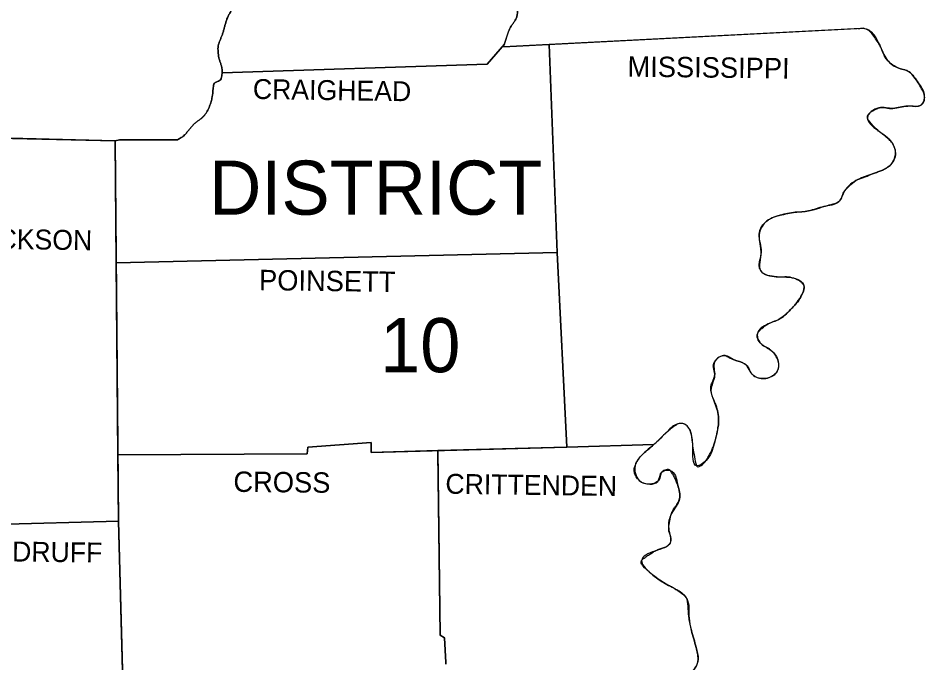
# Model space of a CAD drawing. Extents: x -28335 to 1228743, y -22428 to 152440.
# Drawn here: x 33833 to 38164, y 12816 to 15894 of the extents above; entities that cross this region are included whole.
import ezdxf

# ---------------------------------------------------------------- set-up
doc = ezdxf.new("R2010")
doc.units = 0
doc.layers.add('R_Draft', color=7, linetype='Continuous')
doc.layers.add('R_No Plot', color=7, linetype='Continuous')

msp = doc.modelspace()

# ---------------------------------------------------------------- linework, layer by layer
at = {"layer": 'R_Draft'}
msp.add_line((36152.1, 15757.7), (36176.5, 15832.9), dxfattribs=at)
for points in [[(33229.3, 17459.6), (33220.8, 17391), (33266.1, 17384.2), (33263.8, 17357), (33315.9, 17345.7), (33320.4, 17309.4), (33345.4, 17293.6), (33352.2, 17184.8), (33481.3, 17171.2), (33481.3, 17073.8), (33528.9, 17067), (33528.9, 17028.5), (33569.6, 17017.2), (33567.4, 16885.8), (33603.6, 16879), (33612.7, 16582.3), (33420.1, 16564.2), (33422.4, 16500.7), (33363.5, 16498.5), (33383.9, 15329.6), (34296.8, 15309.2), (34312.6, 13492.5), (33716.9, 13476.6), (33705, 13796)], [(36152.1, 15757.7), (37871.4, 15846.1)], [(34807.8, 15632.9), (36072.8, 15673.9), (36155.9, 15769.7)], [(36369, 15768.9), (36408.1, 14774.6), (36454.1, 13846.6)], [(34593.5, 15313.7), (34317.2, 15313.7), (34296.8, 15309.2)], [(36408.1, 14774.6), (34301.9, 14726.6)], [(34309.9, 13809.5), (35214.2, 13814.2), (35216.5, 13845.9), (35520.1, 13868.5), (35520.1, 13820.9), (36869.5, 13858)], [(35837.1, 13829.7), (35848.5, 12948.8), (35868.9, 12935.2), (35876.1, 12809.9)], [(35837.2, 13820.9), (35848.5, 12948.8), (35868.9, 12935.2), (35875.7, 12817.4)], [(35837.2, 13820.9), (35848.5, 12948.8), (35868.9, 12935.2), (35875.7, 12817.4)], [(35837.2, 13820.9), (35848.5, 12948.8), (35868.9, 12935.2), (35875.7, 12817.4)], [(35837.2, 13820.9), (35848.5, 12948.8), (35868.9, 12935.2), (35875.7, 12817.4)], [(34312.6, 13492.5), (34346.6, 12251.1), (33807.5, 12248.9), (33805.2, 12199), (33648.9, 12190), (33635.3, 11931.7), (33420.5, 11931.7)]]:
    msp.add_lwpolyline(points, dxfattribs=at)
for points in [[(36695.7, 17526.9), (36697.7, 17501.9), (36700.3, 17476.9), (36703.5, 17452.1), (36707.1, 17427.2), (36712.4, 17413.2), (36721.5, 17400.5), (36731.4, 17388.2), (36738.8, 17375.1), (36741.7, 17352.1), (36738.8, 17327.3), (36737.1, 17302.7), (36738.8, 17291), (36743.3, 17280), (36760.5, 17257.7), (36781.8, 17239.2), (36798, 17228.4), (36814.8, 17218.9), (36831.5, 17209.4), (36847.5, 17198.4), (36880.2, 17169.4), (36894.2, 17152.5), (36900.5, 17143), (36906.4, 17132.7), (36914.6, 17113.6), (36919.4, 17094.2), (36921.1, 17074.9), (36920, 17055.7), (36916.1, 17035.9), (36910.5, 17016.2), (36905.1, 16996.4), (36901.9, 16976.4), (36900.6, 16954.4), (36899.9, 16932.3), (36899, 16910.2), (36897.4, 16888.1), (36888.3, 16811.1), (36884, 16775.6), (36880.5, 16758.1), (36878, 16749.4), (36874.7, 16740.8), (36851.1, 16709.5), (36820.3, 16684.2), (36807.3, 16673.9), (36794.1, 16664), (36781, 16653.9), (36768.2, 16643.4), (36720.7, 16595.9), (36711.8, 16583.7), (36704.1, 16570.5), (36696.2, 16557.6), (36686.7, 16546), (36627.8, 16491.7), (36568.9, 16435), (36521.3, 16385.2), (36508.3, 16370.2), (36496.2, 16354.5), (36484.8, 16338.3), (36473.7, 16321.8), (36466.8, 16304.8), (36463.4, 16286), (36459.6, 16267.5), (36456.2, 16259.1), (36451.1, 16251.6), (36438.5, 16238.6), (36425.1, 16226.5), (36411.7, 16214.5), (36399, 16201.7), (36358.2, 16156.4), (36303.8, 16095.3), (36294.9, 16081.3), (36288.7, 16065.6), (36283.3, 16049.4), (36276.7, 16034.1), (36264.5, 16016.2), (36250.3, 15999.2), (36236.3, 15982.2), (36224.6, 15963.9), (36219.7, 15947.6), (36218.3, 15930.1), (36217.3, 15912.4), (36213.2, 15895.9), (36205.9, 15881.9), (36196.9, 15868.4), (36187.6, 15855.1), (36179.3, 15841.5), (36176.5, 15832.9)], [(35025.5, 16260.4), (35006.3, 16232.9), (34990, 16204), (34982.9, 16188.2), (34976.8, 16172), (34970.6, 16155.9), (34962.8, 16140.6), (34950.1, 16121.9), (34936.1, 16104.1), (34921.9, 16086.4), (34908.4, 16068.1), (34886.5, 16033.8), (34876.6, 16016.1), (34867.6, 15997.8), (34864.6, 15986.3), (34863.9, 15974.1), (34863.3, 15961.9), (34860.9, 15950.3), (34853.5, 15934.3), (34844.6, 15918.7), (34836, 15903.1), (34829.1, 15886.9), (34824.4, 15871.1), (34820, 15855.1), (34815.7, 15839.2), (34811, 15823.4), (34806.1, 15809.8), (34800.6, 15796.3), (34795.2, 15782.8), (34790.6, 15769.1), (34788.1, 15755.1), (34787.7, 15740.8), (34788.8, 15726.5), (34790.6, 15712.4), (34793.7, 15698.2), (34798.3, 15684), (34802.9, 15669.9), (34806.5, 15655.8), (34807.9, 15642.9), (34807.5, 15629.7), (34805.6, 15616.6), (34804, 15610.1), (34802, 15603.7), (34795.1, 15596), (34784.5, 15591.2), (34774.1, 15586.5), (34768, 15578.8), (34766.2, 15570.7), (34765, 15562.6), (34763.4, 15546), (34761.8, 15529.4), (34758.9, 15513.1), (34753, 15490.3), (34745.3, 15467.8), (34732.7, 15443.7), (34724.9, 15432.8), (34715.9, 15422.5), (34705.5, 15413.3), (34694.4, 15405.2), (34683.2, 15397.2), (34672.8, 15388.5), (34661.2, 15375.9), (34650.4, 15362.5), (34639.5, 15349.1), (34627.5, 15336.4), (34611.6, 15323.8), (34602.9, 15318.6), (34593.5, 15313.7)], [(37846.5, 15843.8), (37871.4, 15846.1), (37948.5, 15764.5), (37982.4, 15696.6), (38032.3, 15658.1), (38088.9, 15637.7), (38131.9, 15585.6), (38161.4, 15528.9), (38145.5, 15479.1), (38082.1, 15474.6), (38011.9, 15463.3), (37943.9, 15465.5), (37889.6, 15420.2), (37939.4, 15359), (38005.1, 15302.4), (38023.2, 15241.3), (37987, 15182.4), (37914.5, 15150.6), (37844.3, 15123.5), (37780.8, 15069.1), (37751.4, 15017), (37681.2, 14994.3), (37608.7, 14974), (37545.2, 14967.2), (37472.7, 14953.6), (37402.5, 14919.6), (37373.1, 14860.7), (37382.1, 14776.9), (37379.9, 14688.5), (37454.6, 14659.1), (37520.3, 14656.8), (37583.7, 14622.8), (37576.9, 14573), (37529.4, 14509.6), (37472.7, 14459.7), (37416.1, 14434.8), (37364, 14387.3), (37382.1, 14339.7), (37429.7, 14308), (37463.7, 14255.9), (37459.2, 14208.3), (37404.8, 14174.3), (37345.9, 14187.9), (37302.8, 14244.5), (37253, 14262.7), (37210, 14283.1), (37160.1, 14253.6), (37160.1, 14187.9), (37142, 14117.7), (37157.9, 14065.6), (37178.3, 13993.1), (37176, 13938.7), (37157.9, 13861.7), (37119.4, 13782.4), (37074.1, 13757.5), (37055.9, 13843.6), (37046.9, 13913.8), (37019.7, 13954.6), (36983.4, 13956.9), (36935.9, 13922.9), (36883.8, 13870.8), (36818.1, 13814.2), (36779.6, 13757.5), (36799.9, 13687.3), (36849.8, 13669.2), (36888.3, 13682.8), (36908.7, 13728.1), (36947.2, 13734.9), (36983.4, 13664.6)], [(36983.4, 13664.6), (36992.5, 13599), (36954, 13528.7), (36940.4, 13458.5), (36947.2, 13388.3), (36874.7, 13349.8), (36811.3, 13304.5), (36847.5, 13250.1), (36915.5, 13200.3), (36983.4, 13161.8), (37026.5, 13123.3), (37037.8, 13030.4), (37049.1, 12971.5), (37071.8, 12889.9), (37080.8, 12833.3), (37040.1, 12765.3), (36992.5, 12751.8), (36942.7, 12767.6), (36883.8, 12772.1), (36836.2, 12726.8), (36802.2, 12663.4), (36768.2, 12600), (36743.3, 12545.6), (36718.4, 12486.7), (36668.6, 12418.8), (36607.4, 12407.4), (36534.9, 12389.3), (36491.9, 12339.5), (36498.7, 12255.7), (36539.4, 12199), (36571.2, 12128.8), (36593.8, 12067.6), (36582.5, 11990.6), (36550.8, 11934), (36510, 11900), (36491.9, 11827.5), (36462.4, 11773.2), (36435.2, 11755), (36380.9, 11759.6), (36322, 11770.9), (36272.1, 11766.4), (36224.6, 11741.4), (36177, 11757.3), (36127.2, 11811.7), (36086.4, 11852.4), (36041.1, 11868.3), (35993.5, 11843.4), (35984.4, 11768.6), (36007.1, 11691.6), (36027.5, 11587.4), (36007.1, 11524), (36000.3, 11419.8)]]:
    msp.add_spline(points, degree=3, dxfattribs=at)
at = {"layer": 'R_No Plot'}
for p, q in [((36155.9, 15769.7), (36176.5, 15832.9)), ((36152.1, 15757.7), (36155.9, 15769.7)), ((36369, 15768.9), (36152.1, 15757.7)), ((36408.1, 14774.6), (36369, 15768.9)), ((34296.8, 15309.2), (34301.9, 14726.6)), ((34301.9, 14726.6), (36408.1, 14774.6)), ((36408.1, 14774.6), (34301.9, 14726.6)), ((36454.1, 13846.6), (36408.1, 14774.6)), ((34301.9, 14726.6), (34309.9, 13809.5)), ((35837.1, 13829.7), (35837.2, 13820.9)), ((35837.2, 13820.9), (35837.1, 13829.7)), ((35837.2, 13820.9), (35848.5, 12948.8)), ((35848.5, 12948.8), (35837.2, 13820.9)), ((36454.1, 13846.6), (36869.5, 13858)), ((34309.9, 13809.5), (34312.6, 13492.5)), ((34312.6, 13492.5), (34332.2, 12778.8)), ((34332.2, 12778.8), (34312.6, 13492.5)), ((35848.5, 12948.8), (35868.9, 12935.2)), ((35868.9, 12935.2), (35848.5, 12948.8)), ((35868.9, 12935.2), (35875.7, 12817.4)), ((35875.7, 12817.4), (35868.9, 12935.2)), ((35875.7, 12817.4), (35876.1, 12809.9)), ((35876.1, 12809.9), (35875.7, 12817.4))]:
    msp.add_line(p, q, dxfattribs=at)
for points in [[(33611.2, 16630), (33612.7, 16582.3), (33420.1, 16564.2), (33422.4, 16500.7), (33363.5, 16498.5), (33383.9, 15329.6), (34296.8, 15309.2)], [(37871.4, 15846.1), (37857, 15845.3), (36369, 15768.9)], [(34807.8, 15632.9), (36072.8, 15673.9), (36155.9, 15769.7)], [(36155.9, 15769.7), (36072.8, 15673.9), (34807.8, 15632.9)], [(36369, 15768.9), (36408.1, 14774.6), (36454.1, 13846.6)], [(33705, 13796), (33716.9, 13476.6), (34312.6, 13492.5), (34309.9, 13809.5), (34301.9, 14726.6), (34296.8, 15309.2), (33793.1, 15320.5)], [(34296.8, 15309.2), (34317.2, 15313.7), (34593.5, 15313.7)], [(34593.5, 15313.7), (34317.2, 15313.7), (34296.8, 15309.2)], [(34309.9, 13809.5), (35214.2, 13814.2), (35216.5, 13845.9), (35520.1, 13868.5), (35520.1, 13820.9), (36454.1, 13846.6)], [(35837.1, 13829.7), (35520.1, 13820.9), (35520.1, 13868.5), (35216.5, 13845.9), (35214.2, 13814.2), (34309.9, 13809.5)], [(36869.5, 13858), (36454.1, 13846.6), (35837.1, 13829.7)], [(36869.5, 13858), (36869.5, 13858)], [(36869.5, 13858), (36869.5, 13858)], [(34312.6, 13492.5), (33716.9, 13476.6), (33705, 13796)]]:
    msp.add_lwpolyline(points, dxfattribs=at)
for points in [[(36176.5, 15832.9), (36179.3, 15841.5), (36187.6, 15855.1), (36196.9, 15868.4), (36205.9, 15881.9), (36213.2, 15895.9), (36217.3, 15912.4), (36218.3, 15930.1), (36219.7, 15947.6), (36224.6, 15963.9), (36236.3, 15982.2), (36250.3, 15999.2), (36264.5, 16016.2), (36276.7, 16034.1), (36283.3, 16049.4), (36288.7, 16065.6), (36294.9, 16081.3), (36303.8, 16095.3), (36358.2, 16156.4), (36399, 16201.7), (36411.7, 16214.5), (36425.1, 16226.5), (36438.5, 16238.6), (36451.1, 16251.6), (36456.2, 16259.1), (36459.6, 16267.5), (36463.4, 16286), (36466.8, 16304.8), (36473.7, 16321.8), (36484.8, 16338.3), (36496.2, 16354.5), (36508.3, 16370.2), (36521.3, 16385.2), (36532.9, 16397.8)], [(34794.6, 15595.7), (34795.1, 15596), (34802, 15603.7), (34804, 15610.1), (34805.6, 15616.6), (34807.5, 15629.7), (34807.9, 15642.9), (34806.5, 15655.8), (34802.9, 15669.9), (34798.3, 15684), (34793.7, 15698.2), (34790.6, 15712.4), (34788.8, 15726.5), (34787.7, 15740.8), (34788.1, 15755.1), (34790.6, 15769.1), (34795.2, 15782.8), (34800.6, 15796.3), (34806.1, 15809.8), (34811, 15823.4), (34815.7, 15839.2), (34820, 15855.1), (34824.4, 15871.1), (34829.1, 15886.9), (34836, 15903.1), (34844.6, 15918.7), (34853.5, 15934.3), (34857.3, 15941.7)], [(34857.3, 15941.7), (34853.5, 15934.3), (34844.6, 15918.7), (34836, 15903.1), (34829.1, 15886.9), (34824.4, 15871.1), (34820, 15855.1), (34815.7, 15839.2), (34811, 15823.4), (34806.1, 15809.8), (34800.6, 15796.3), (34795.2, 15782.8), (34790.6, 15769.1), (34788.1, 15755.1), (34787.7, 15740.8), (34788.8, 15726.5), (34790.6, 15712.4), (34793.7, 15698.2), (34798.3, 15684), (34802.9, 15669.9), (34806.5, 15655.8), (34807.9, 15642.9), (34807.8, 15632.9)], [(37637.3, 14981.3), (37681.2, 14994.3), (37716.5, 15004.7), (37751.4, 15017), (37761.9, 15026.4), (37768, 15040.5), (37773.1, 15055.9), (37780.8, 15069.1), (37795.2, 15084.5), (37810.1, 15099.6), (37844.3, 15123.5), (37879.3, 15137.3), (37914.5, 15150.6), (37950.9, 15165.1), (37987, 15182.4), (38001, 15193.7), (38011.6, 15208.4), (38023.2, 15241.3), (38023.9, 15256.6), (38020.9, 15272.6), (38014.6, 15288.3), (38005.1, 15302.4), (37989.3, 15318.2), (37972.6, 15331.6), (37955.7, 15344.5), (37939.4, 15359), (37908.7, 15389.5), (37896.2, 15405), (37889.6, 15420.2), (37889.4, 15423.6), (37890, 15426.9), (37893.4, 15433.6), (37906.7, 15446.3), (37925, 15457.3), (37943.9, 15465.5), (37952.4, 15467.6), (37960.9, 15468.2), (37978, 15466.3), (37995, 15463.4), (38011.9, 15463.3), (38047, 15468.9), (38082.1, 15474.6), (38097.9, 15474.8), (38113.8, 15473.4), (38129.7, 15473.7), (38145.5, 15479.1), (38148.6, 15481.1), (38151.4, 15483.5), (38156, 15488.9), (38161.9, 15501.9), (38161.4, 15528.9), (38148.9, 15557.4), (38131.9, 15585.6), (38112.2, 15613.6), (38088.9, 15637.7), (38075.7, 15644.9), (38061.1, 15648.9), (38046.2, 15652.4), (38032.3, 15658.1), (37982.4, 15696.6), (37972.1, 15712.6), (37964.6, 15729.9), (37957.5, 15747.6), (37948.5, 15764.5), (37932.6, 15789.7), (37915.8, 15814.5), (37896.1, 15834.8), (37871.4, 15846.1)], [(34593.5, 15313.7), (34602.9, 15318.6), (34611.6, 15323.8), (34627.5, 15336.4), (34639.5, 15349.1), (34650.4, 15362.5), (34661.2, 15375.9), (34672.8, 15388.5), (34683.2, 15397.2), (34694.4, 15405.2), (34705.5, 15413.3), (34715.9, 15422.5), (34724.9, 15432.8), (34732.7, 15443.7), (34745.3, 15467.8), (34753, 15490.3), (34758.9, 15513.1), (34761.8, 15529.4), (34763.4, 15546), (34765, 15562.6), (34766.2, 15570.7), (34768, 15578.8), (34774.1, 15586.5), (34784.5, 15591.2), (34794.6, 15595.7)], [(34794.6, 15595.7), (34784.5, 15591.2), (34774.1, 15586.5), (34768, 15578.8), (34766.2, 15570.7), (34765, 15562.6), (34763.4, 15546), (34761.8, 15529.4), (34758.9, 15513.1), (34753, 15490.3), (34745.3, 15467.8), (34732.7, 15443.7), (34724.9, 15432.8), (34715.9, 15422.5), (34705.5, 15413.3), (34694.4, 15405.2), (34683.2, 15397.2), (34672.8, 15388.5), (34661.2, 15375.9), (34650.4, 15362.5), (34639.5, 15349.1), (34627.5, 15336.4), (34611.6, 15323.8), (34602.9, 15318.6), (34593.5, 15313.7)], [(34807.8, 15632.9), (34807.5, 15629.7), (34805.6, 15616.6), (34804, 15610.1), (34802, 15603.7), (34795.1, 15596), (34794.6, 15595.7)], [(37249.7, 14264.1), (37253, 14262.7), (37302.8, 14244.5), (37315.8, 14233.6), (37324.7, 14217.8), (37333.5, 14201.2), (37345.9, 14187.9), (37374.9, 14175.3), (37404.8, 14174.3), (37433.6, 14185.5), (37446.9, 14195.3), (37459.2, 14208.3), (37463.7, 14255.9), (37429.7, 14308), (37418.5, 14317), (37406.1, 14323.8), (37393.6, 14330.7), (37382.1, 14339.7), (37365.6, 14363.3), (37364, 14387.3), (37373.6, 14400.7), (37386.1, 14413.2), (37416.1, 14434.8), (37430.3, 14441.7), (37444.9, 14447), (37459.3, 14452.4), (37472.7, 14459.7), (37529.4, 14509.6), (37542.7, 14524.6), (37554.9, 14540.3), (37576.9, 14573), (37588, 14598), (37588.7, 14611.1), (37583.7, 14622.8), (37577.3, 14629.8), (37570.3, 14635.9), (37554.9, 14645.5), (37520.3, 14656.8), (37503.9, 14658.5), (37487.5, 14658.2), (37471, 14657.8), (37454.6, 14659.1), (37434, 14661.9), (37413.3, 14665.6), (37394.6, 14673.4), (37379.9, 14688.5), (37377, 14694), (37374.9, 14699.5), (37373, 14710.5), (37375, 14732.6), (37380, 14754.8), (37382.1, 14776.9), (37379.9, 14797.8), (37376.8, 14818.8), (37374, 14839.8), (37373.1, 14860.7), (37375.2, 14876.7), (37381, 14892), (37402.5, 14919.6), (37410.8, 14926.5), (37419.1, 14932.5), (37436.3, 14941.9), (37454.1, 14948.6), (37472.7, 14953.6), (37508.9, 14961.1), (37545.2, 14967.2), (37561.1, 14968.8), (37577.1, 14969.9), (37608.7, 14974), (37637.3, 14981.3)], [(36869.5, 13858), (36883.8, 13870.8), (36935.9, 13922.9), (36958.8, 13941.4), (36971, 13949.4), (36983.4, 13956.9), (37001.5, 13961), (37019.7, 13954.6), (37029.4, 13945.8), (37037.4, 13936.1), (37043.3, 13925.4), (37046.9, 13913.8), (37049.7, 13896.3), (37051.7, 13878.7), (37055.9, 13843.6), (37063.4, 13799.9), (37074.1, 13757.5), (37077.1, 13753.3), (37082.1, 13752.5), (37095.2, 13758.3), (37119.4, 13782.4), (37130.9, 13801.7), (37141.4, 13821.1), (37150.5, 13841), (37157.9, 13861.7), (37176, 13938.7), (37178.3, 13993.1), (37157.9, 14065.6), (37142, 14117.7), (37141.8, 14135.1), (37147.4, 14152.7), (37154.9, 14170.3), (37160.1, 14187.9), (37160.4, 14195.9), (37159.3, 14204.1), (37155.4, 14220.6), (37153.8, 14237.2), (37160.1, 14253.6), (37165.6, 14260.6), (37171.5, 14267), (37183.8, 14277.5), (37210, 14283.1), (37229.8, 14274.2), (37249.7, 14264.1)], [(36983.4, 13664.6), (36968.6, 13701.9), (36958.9, 13719.1), (36953.3, 13727.2), (36947.2, 13734.9), (36938.9, 13739.2), (36928.2, 13738.4), (36917.4, 13734.1), (36908.7, 13728.1), (36902.8, 13717.9), (36900, 13705.2), (36896.4, 13692.6), (36888.3, 13682.8), (36878.7, 13677.2), (36869, 13672.9), (36859.4, 13670.2), (36849.8, 13669.2), (36837.3, 13669.8), (36824.8, 13672.5), (36812.4, 13678), (36799.9, 13687.3), (36795.9, 13691.3), (36792.1, 13695.5), (36785.9, 13704.2), (36777.8, 13722.4), (36775.7, 13740.7), (36779.6, 13757.5), (36786.8, 13772.4), (36795.6, 13787.1), (36818.1, 13814.2), (36843.7, 13836.6), (36869.5, 13858)], [(36613.9, 12408.7), (36641.4, 12412.1), (36668.6, 12418.8), (36673.4, 12421.1), (36678, 12423.8), (36686.1, 12430.5), (36699.3, 12447.2), (36709.6, 12466.8), (36718.4, 12486.7), (36743.3, 12545.6), (36768.2, 12600), (36802.2, 12663.4), (36836.2, 12726.8), (36856, 12753.9), (36883.8, 12772.1), (36890.9, 12774), (36898.3, 12774.8), (36913.2, 12773.9), (36942.7, 12767.6), (36955.1, 12764), (36967.6, 12759.3), (36980, 12754.8), (36992.5, 12751.8), (37004.4, 12751.1), (37016.3, 12753), (37028.2, 12757.7), (37040.1, 12765.3), (37049.1, 12772.9), (37057.2, 12780.7), (37070.2, 12797), (37078.3, 12814.5), (37080.8, 12833.3), (37079.9, 12847.5), (37078, 12861.7), (37071.8, 12889.9), (37049.1, 12971.5), (37043.2, 13000.9), (37037.8, 13030.4), (37035.1, 13053.5), (37034, 13076.9), (37031.9, 13100.2), (37026.5, 13123.3), (37023.4, 13129.9), (37019.3, 13135.7), (37008.7, 13145.7), (36983.4, 13161.8), (36966.5, 13171.7), (36949.4, 13181), (36932.3, 13190.3), (36915.5, 13200.3), (36880.9, 13223.9), (36847.5, 13250.1), (36818.7, 13277.3), (36809.7, 13291.9), (36811.3, 13304.5), (36817, 13310.8), (36823.7, 13316.8), (36839.7, 13328.3), (36857.3, 13339.1), (36874.7, 13349.8), (36883.8, 13354.7), (36893.2, 13358.5), (36912.6, 13365), (36931.2, 13373.5), (36947.2, 13388.3), (36949.8, 13392.5), (36951.5, 13396.7), (36952.6, 13405.3), (36948.8, 13423), (36942.5, 13440.9), (36940.4, 13458.5), (36945.8, 13493.7), (36954, 13528.7), (36962.5, 13547.1), (36974.2, 13564.2), (36985.4, 13581.1), (36992.5, 13599), (36983.4, 13664.6)]]:
    msp.add_spline(points, degree=3, dxfattribs=at)

# ---------------------------------------------------------------- texts
at = {"layer": 'R_Draft'}
for s, height, rotation, p in [('MISSISSIPPI', 97.394, 359.3097, (36743.3, 15615)), ('CRAIGHEAD', 95.15, 359.1159, (34953.7, 15508.6)), ('JACKSON', 95.12, 359.1352, (33585.5, 14795)), ('POINSETT', 97.4, 359.1987, (34983.2, 14595.7)), ('CROSS', 97.4, 359.384, (34860.9, 13632.9)), ('CRITTENDEN', 95.15, 359.213, (35873.4, 13623.9)), ('WOODRUFF', 95.12, 359.2748, (33485.8, 13304.5))]:
    msp.add_text(s, height=height, rotation=rotation, dxfattribs=at).set_placement(p)
for s, p in [('DISTRICT', (34745.3, 14955.8)), ('10', (35561.5, 14203.8))]:
    msp.add_text(s, height=258.24, dxfattribs=at).set_placement(p)

doc.saveas('drawing.dxf')
